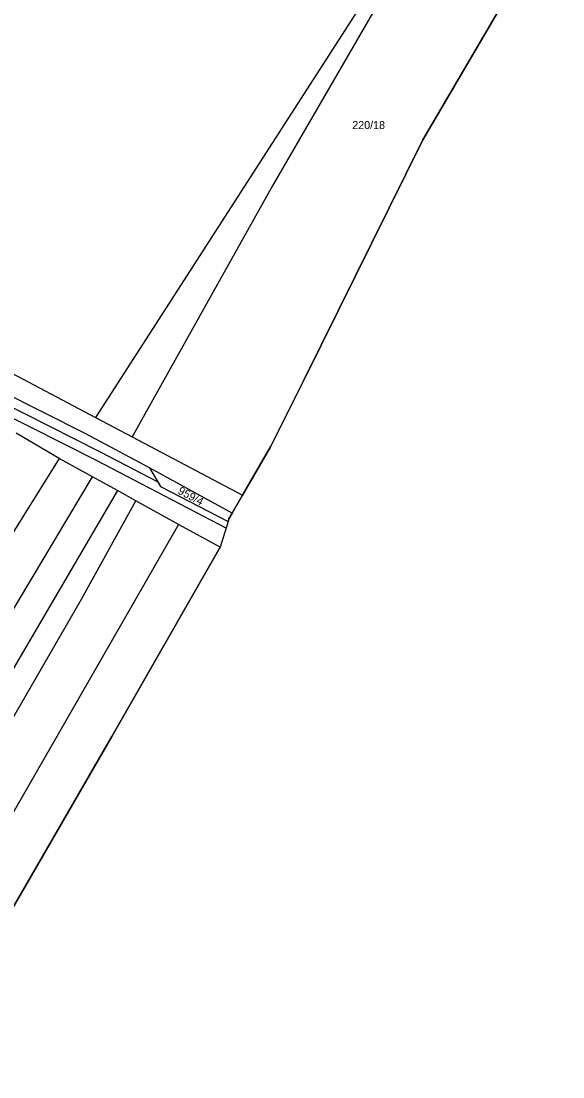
# Model space of a CAD drawing. Extents: x -749173 to -746119, y -1132678 to -1130338.
# Drawn here: x -746740.4 to -746625.4, y -1131504.5 to -1131280.2 of the extents above; entities that cross this region are included whole.
import ezdxf

# ---------------------------------------------------------------- set-up
doc = ezdxf.new("R2010")
doc.units = 0
for name, color, linetype in [('Vrstva 1', 7, 'Continuous'), ('Vrstva 13', 7, 'Continuous'), ('Vrstva 18', 7, 'Continuous'), ('Vrstva 30', 7, 'Continuous'), ('Vrstva 52', 7, 'Continuous'), ('Vrstva 6', 7, 'Continuous')]:
    doc.layers.add(name, color=color, linetype=linetype)

msp = doc.modelspace()

# ---------------------------------------------------------------- linework, layer by layer
at = {"layer": 'Vrstva 1'}
for points in [[(-746751.91, -1131349.96), (-746724.6, -1131364.42)], [(-746726.64, -1131367.9), (-746753.98, -1131354.19)], [(-746724.6, -1131364.42), (-746716.79, -1131368.55)], [(-746732.32, -1131373.1), (-746741.44, -1131367.75)], [(-746713.13, -1131375.09), (-746726.64, -1131367.9)], [(-746716.79, -1131368.55), (-746693.38, -1131380.95)], [(-746725.23, -1131377.02), (-746732.32, -1131373.1)], [(-746695.57, -1131384.74), (-746713.13, -1131375.09)], [(-746719.96, -1131379.93), (-746725.23, -1131377.02)], [(-746716.03, -1131382.11), (-746719.96, -1131379.93)], [(-746706.95, -1131387.13), (-746716.03, -1131382.11)], [(-746698.14, -1131392), (-746706.95, -1131387.13)]]:
    msp.add_lwpolyline(points, dxfattribs=at)
at = {"layer": 'Vrstva 13'}
for points in [[(-746655.09, -1131305.42), (-746625.38, -1131254.67)], [(-746680.29, -1131356.36), (-746655.09, -1131305.42)], [(-746687.43, -1131370.65), (-746680.29, -1131356.36)], [(-746693.38, -1131380.95), (-746687.43, -1131370.65)], [(-746695.57, -1131384.74), (-746693.38, -1131380.95)], [(-746696.27, -1131385.95), (-746695.57, -1131384.74)], [(-746696.44, -1131386.49), (-746698.14, -1131392)], [(-746696.44, -1131386.49), (-746696.27, -1131385.95)], [(-746721.13, -1131432.18), (-746698.14, -1131392)], [(-746762.97, -1131504.51), (-746721.13, -1131432.18)]]:
    msp.add_lwpolyline(points, dxfattribs=at)
at = {"layer": 'Vrstva 30'}
for p, q in [((-746756.57, -1131355.05), (-746723.61, -1131371.7)), ((-746724.53, -1131373.48), (-746757.37, -1131356.89)), ((-746723.61, -1131371.7), (-746711.39, -1131378.08)), ((-746696.88, -1131387.91), (-746724.53, -1131373.48)), ((-746711.39, -1131378.08), (-746710.83, -1131379.05)), ((-746710.83, -1131379.05), (-746696.44, -1131386.49)), ((-746696.44, -1131386.49), (-746696.88, -1131387.91)), ((-746696.44, -1131386.49), (-746696.27, -1131385.95))]:
    msp.add_line(p, q, dxfattribs=at)
at = {"layer": 'Vrstva 52'}
msp.add_lwpolyline([(-746625.38, -1131254.67), (-746655.09, -1131305.42), (-746680.29, -1131356.36), (-746687.43, -1131370.65), (-746693.38, -1131380.95), (-746695.57, -1131384.74), (-746696.27, -1131385.95), (-746696.44, -1131386.49), (-746698.14, -1131392), (-746721.13, -1131432.18), (-746762.97, -1131504.51)], dxfattribs=at)
at = {"layer": 'Vrstva 6'}
for points in [[(-746657.1, -1131263.41), (-746686.96, -1131315.09)], [(-746667, -1131274.84), (-746724.6, -1131364.42)], [(-746686.96, -1131315.09), (-746716.79, -1131368.55)], [(-746732.32, -1131373.1), (-746755.61, -1131410.4)], [(-746713.13, -1131375.09), (-746710.83, -1131379.05)], [(-746743.56, -1131407.78), (-746725.23, -1131377.02)], [(-746719.96, -1131379.93), (-746754.34, -1131438.63)], [(-746710.83, -1131379.05), (-746696.44, -1131386.49)], [(-746727.58, -1131402.99), (-746716.03, -1131382.11)], [(-746706.95, -1131387.13), (-746735.03, -1131436.04)], [(-746759.79, -1131458.77), (-746727.58, -1131402.99)], [(-746735.03, -1131436.04), (-746771.27, -1131499.19)]]:
    msp.add_lwpolyline(points, dxfattribs=at)

# ---------------------------------------------------------------- texts
at = {"layer": 'Vrstva 18'}
msp.add_text('220/18', height=1.7, dxfattribs=at).set_placement((-746670.09, -1131303.14))
msp.add_text('959/4', height=1.7, rotation=331.6992, dxfattribs=at).set_placement((-746707.26, -1131380.5))

doc.saveas('drawing.dxf')
